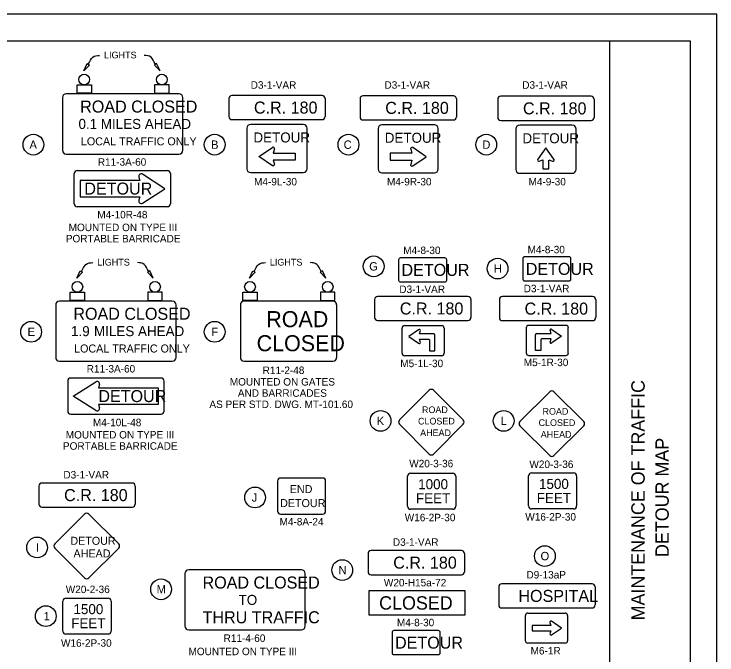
# Model space of a CAD drawing. Extents: x 1 to 1971, y -2 to 1107.
# Drawn here: x 1672.33 to 1685.46, y 1094.62 to 1106.6 of the extents above; entities that cross this region are included whole.
import ezdxf

# ---------------------------------------------------------------- set-up
doc = ezdxf.new("R2010")
doc.units = 0
for name, color, linetype in [('SH_Border', 7, 'Continuous'), ('SH_Cut_Line', 7, 'Continuous'), ('SH_Data', 7, 'Continuous'), ('SH_Text', 7, 'Continuous'), ('SN_P_Signs', 7, 'Continuous'), ('SN_P_Text', 7, 'Continuous')]:
    doc.layers.add(name, color=color, linetype=linetype)

msp = doc.modelspace()

# ---------------------------------------------------------------- linework, layer by layer
at = {"layer": 'SH_Border'}
msp.add_line((1683.463, 1085.101), (1683.463, 1106.101), dxfattribs=at)
msp.add_lwpolyline([(1652.963, 1106.101), (1684.963, 1106.101), (1684.963, 1085.101), (1652.963, 1085.101)], close=True, dxfattribs=at)
at = {"layer": 'SH_Cut_Line'}
msp.add_lwpolyline([(1651.463, 1084.601), (1685.463, 1084.601), (1685.463, 1106.601), (1651.463, 1106.601)], close=True, dxfattribs=at)
at = {"layer": 'SH_Text'}
for centre in [(1672.689, 1104.158), (1676.077, 1104.158), (1678.577, 1104.158), (1681.152, 1104.158), (1679.048, 1101.882), (1681.364, 1101.84), (1672.647, 1100.658), (1676.077, 1100.658), (1679.177, 1098.992), (1681.477, 1098.992), (1676.832, 1097.56), (1672.758, 1096.626), (1682.247, 1096.464), (1678.461, 1096.202), (1675.075, 1095.843), (1672.921, 1095.341)]:
    msp.add_circle(centre, 0.194, dxfattribs=at)
at = {"layer": 'SN_P_Signs'}
for p, q in [((1676.903, 1103.936), (1677.156, 1104.108)), ((1677.195, 1104.079), (1677.17, 1104.002)), ((1679.74, 1104.073), (1679.764, 1103.997)), ((1680.031, 1103.931), (1679.779, 1104.102)), ((1682.267, 1104.099), (1682.116, 1103.884)), ((1682.418, 1103.884), (1682.267, 1104.099)), ((1677.156, 1103.765), (1676.903, 1103.936)), ((1677.17, 1104.002), (1677.578, 1104.002)), ((1677.578, 1104.002), (1677.578, 1103.871)), ((1679.764, 1103.997), (1679.356, 1103.997)), ((1679.356, 1103.997), (1679.356, 1103.865)), ((1679.779, 1103.76), (1680.031, 1103.931)), ((1677.578, 1103.871), (1677.17, 1103.871)), ((1677.17, 1103.871), (1677.195, 1103.794)), ((1679.356, 1103.865), (1679.764, 1103.865)), ((1679.764, 1103.865), (1679.74, 1103.789)), ((1682.141, 1103.85), (1682.21, 1103.872)), ((1682.21, 1103.872), (1682.21, 1103.871)), ((1682.21, 1103.871), (1682.21, 1103.705)), ((1682.324, 1103.872), (1682.393, 1103.85)), ((1682.21, 1103.705), (1682.324, 1103.705)), ((1674.66, 1103.552), (1674.68, 1103.49)), ((1675.148, 1103.335), (1674.727, 1103.604)), ((1674.68, 1103.49), (1673.564, 1103.49)), ((1673.564, 1103.49), (1673.564, 1103.181)), ((1674.727, 1103.067), (1675.148, 1103.335)), ((1673.564, 1103.181), (1674.68, 1103.181)), ((1674.68, 1103.181), (1674.66, 1103.118)), ((1679.624, 1100.774), (1680.321, 1100.774)), ((1682.641, 1100.779), (1681.944, 1100.779)), ((1679.579, 1100.256), (1679.579, 1100.729)), ((1679.889, 1100.695), (1679.705, 1100.57)), ((1679.902, 1100.619), (1679.921, 1100.682)), ((1680.366, 1100.729), (1680.366, 1100.256)), ((1681.899, 1100.734), (1681.899, 1100.262)), ((1682.096, 1100.625), (1682.363, 1100.625)), ((1682.096, 1100.625), (1682.096, 1100.625)), ((1682.363, 1100.625), (1682.344, 1100.688)), ((1682.376, 1100.701), (1682.56, 1100.575)), ((1682.686, 1100.262), (1682.686, 1100.734)), ((1679.705, 1100.57), (1679.889, 1100.444)), ((1680.17, 1100.619), (1679.902, 1100.619)), ((1679.921, 1100.457), (1679.902, 1100.52)), ((1679.902, 1100.52), (1680.078, 1100.52)), ((1680.092, 1100.506), (1680.092, 1100.302)), ((1680.17, 1100.619), (1680.17, 1100.619)), ((1680.191, 1100.302), (1680.191, 1100.598)), ((1682.075, 1100.308), (1682.075, 1100.604)), ((1682.173, 1100.512), (1682.173, 1100.308)), ((1682.363, 1100.526), (1682.187, 1100.526)), ((1682.344, 1100.463), (1682.363, 1100.526)), ((1682.56, 1100.575), (1682.376, 1100.45)), ((1680.092, 1100.302), (1680.191, 1100.302)), ((1680.092, 1100.302), (1680.191, 1100.302)), ((1682.173, 1100.308), (1682.075, 1100.308)), ((1680.321, 1100.211), (1679.624, 1100.211)), ((1681.944, 1100.217), (1682.641, 1100.217)), ((1673.434, 1099.456), (1673.856, 1099.725)), ((1673.923, 1099.673), (1673.903, 1099.611)), ((1673.903, 1099.611), (1675.018, 1099.611)), ((1675.018, 1099.611), (1675.018, 1099.301)), ((1673.856, 1099.187), (1673.434, 1099.456)), ((1675.018, 1099.301), (1673.903, 1099.301)), ((1673.903, 1099.301), (1673.923, 1099.239)), ((1681.928, 1095.399), (1682.626, 1095.399)), ((1681.883, 1094.881), (1681.883, 1095.354)), ((1682.558, 1095.117), (1682.372, 1095.245)), ((1682.671, 1095.354), (1682.671, 1094.881)), ((1682.361, 1095.167), (1682.01, 1095.167)), ((1682.01, 1095.167), (1682.01, 1095.068)), ((1682.343, 1095.224), (1682.361, 1095.167)), ((1682.374, 1094.992), (1682.558, 1095.117)), ((1682.01, 1095.068), (1682.361, 1095.068)), ((1682.361, 1095.068), (1682.343, 1095.011)), ((1682.626, 1094.836), (1681.928, 1094.836))]:
    msp.add_line(p, q, dxfattribs=at)
for points in [[(1673.735, 1105.647), (1673.63, 1105.536), (1673.694, 1105.675)], [(1674.95, 1105.647), (1675.056, 1105.536), (1674.992, 1105.675)], [(1673.504, 1105.12), (1673.504, 1105.275), (1673.773, 1105.275), (1673.773, 1105.12)], [(1675.224, 1105.12), (1675.224, 1105.275), (1674.955, 1105.275), (1674.955, 1105.12)], [(1673.608, 1101.772), (1673.503, 1101.661), (1673.566, 1101.801)], [(1674.823, 1101.772), (1674.928, 1101.661), (1674.864, 1101.801)], [(1676.834, 1101.772), (1676.729, 1101.661), (1676.793, 1101.801)], [(1678.049, 1101.772), (1678.154, 1101.661), (1678.091, 1101.801)], [(1673.376, 1101.245), (1673.376, 1101.401), (1673.645, 1101.401), (1673.645, 1101.245)], [(1675.097, 1101.245), (1675.097, 1101.401), (1674.828, 1101.401), (1674.828, 1101.245)], [(1676.603, 1101.245), (1676.603, 1101.401), (1676.872, 1101.401), (1676.872, 1101.245)], [(1678.323, 1101.245), (1678.323, 1101.401), (1678.054, 1101.401), (1678.054, 1101.245)], [(1678.959, 1095.363), (1680.759, 1095.363), (1680.759, 1095.813), (1678.959, 1095.813)]]:
    msp.add_lwpolyline(points, close=True, dxfattribs=at)
for points in [[(1675.413, 1105.108), (1673.303, 1105.108)], [(1673.233, 1105.038), (1673.233, 1104.053)], [(1675.483, 1104.053), (1675.483, 1105.038)], [(1676.34, 1105.02), (1676.34, 1104.683)], [(1678.084, 1105.076), (1676.397, 1105.076)], [(1678.14, 1105.02), (1678.14, 1104.683)], [(1678.794, 1105.015), (1678.794, 1104.677)], [(1680.538, 1105.071), (1678.85, 1105.071)], [(1680.594, 1105.015), (1680.594, 1104.677)], [(1681.367, 1105.006), (1681.367, 1104.668)], [(1683.111, 1105.062), (1681.423, 1105.062)], [(1683.167, 1105.006), (1683.167, 1104.668)], [(1676.397, 1104.626), (1678.084, 1104.626)], [(1678.85, 1104.621), (1680.538, 1104.621)], [(1681.423, 1104.612), (1683.111, 1104.612)], [(1676.678, 1104.464), (1676.678, 1103.708)], [(1677.731, 1104.536), (1676.75, 1104.536)], [(1677.803, 1103.708), (1677.803, 1104.464)], [(1679.131, 1104.459), (1679.131, 1103.703)], [(1680.184, 1104.531), (1679.203, 1104.531)], [(1680.256, 1103.703), (1680.256, 1104.459)], [(1681.705, 1104.45), (1681.705, 1103.694)], [(1682.758, 1104.522), (1681.777, 1104.522)], [(1682.83, 1103.694), (1682.83, 1104.45)], [(1673.303, 1103.983), (1675.413, 1103.983)], [(1682.324, 1103.705), (1682.324, 1103.871)], [(1673.508, 1103.673), (1675.195, 1103.673)], [(1673.452, 1103.054), (1673.452, 1103.617)], [(1675.252, 1103.617), (1675.252, 1103.054)], [(1676.75, 1103.636), (1677.731, 1103.636)], [(1679.203, 1103.631), (1680.184, 1103.631)], [(1681.777, 1103.622), (1682.758, 1103.622)], [(1675.195, 1102.998), (1673.508, 1102.998)], [(1679.514, 1102.005), (1679.514, 1101.627)], [(1680.378, 1102.041), (1679.55, 1102.041)], [(1680.414, 1101.627), (1680.414, 1102.005)], [(1681.835, 1102.025), (1681.835, 1101.647)], [(1682.699, 1102.061), (1681.871, 1102.061)], [(1682.735, 1101.647), (1682.735, 1102.025)], [(1679.55, 1101.591), (1680.378, 1101.591)], [(1681.871, 1101.611), (1682.699, 1101.611)], [(1680.81, 1101.32), (1679.122, 1101.32)], [(1683.14, 1101.317), (1681.453, 1101.317)], [(1673.106, 1101.163), (1673.106, 1100.179)], [(1675.285, 1101.233), (1673.176, 1101.233)], [(1675.356, 1100.179), (1675.356, 1101.163)], [(1676.557, 1101.163), (1676.557, 1100.179)], [(1678.286, 1101.233), (1676.627, 1101.233)], [(1678.357, 1100.179), (1678.357, 1101.163)], [(1679.066, 1101.263), (1679.066, 1100.926)], [(1680.866, 1101.263), (1680.866, 1100.926)], [(1681.397, 1101.261), (1681.397, 1100.923)], [(1683.197, 1101.261), (1683.197, 1100.923)], [(1679.122, 1100.87), (1680.81, 1100.87)], [(1681.453, 1100.867), (1683.14, 1100.867)], [(1673.176, 1100.108), (1675.285, 1100.108)], [(1676.627, 1100.108), (1678.286, 1100.108)], [(1673.331, 1099.737), (1673.331, 1099.175)], [(1675.074, 1099.794), (1673.387, 1099.794)], [(1675.131, 1099.175), (1675.131, 1099.737)], [(1679.528, 1099.009), (1680.085, 1099.566)], [(1680.164, 1099.566), (1680.721, 1099.009)], [(1681.781, 1098.98), (1682.338, 1099.537)], [(1682.418, 1099.537), (1682.974, 1098.98)], [(1673.387, 1099.119), (1675.074, 1099.119)], [(1680.085, 1098.373), (1679.528, 1098.929)], [(1680.721, 1098.929), (1680.164, 1098.373)], [(1682.338, 1098.343), (1681.781, 1098.9)], [(1682.974, 1098.9), (1682.418, 1098.343)], [(1679.739, 1098.014), (1680.526, 1098.014)], [(1681.997, 1098.02), (1682.785, 1098.02)], [(1677.25, 1097.865), (1677.25, 1097.307)], [(1678.092, 1097.924), (1677.309, 1097.924)], [(1678.15, 1097.307), (1678.15, 1097.865)], [(1679.683, 1097.395), (1679.683, 1097.958)], [(1680.583, 1097.958), (1680.583, 1097.395)], [(1681.941, 1097.401), (1681.941, 1097.964)], [(1682.841, 1097.964), (1682.841, 1097.401)], [(1672.792, 1097.773), (1672.792, 1097.436)], [(1674.536, 1097.83), (1672.848, 1097.83)], [(1674.592, 1097.773), (1674.592, 1097.436)], [(1672.848, 1097.38), (1674.536, 1097.38)], [(1682.785, 1097.345), (1681.997, 1097.345)], [(1673.091, 1096.693), (1673.647, 1097.25)], [(1673.727, 1097.25), (1674.284, 1096.693)], [(1677.309, 1097.249), (1678.092, 1097.249)], [(1680.526, 1097.339), (1679.739, 1097.339)], [(1673.647, 1096.057), (1673.091, 1096.614)], [(1674.284, 1096.614), (1673.727, 1096.057)], [(1680.687, 1096.566), (1678.999, 1096.566)], [(1678.943, 1096.51), (1678.943, 1096.172)], [(1680.743, 1096.51), (1680.743, 1096.172)], [(1677.7, 1096.207), (1675.591, 1096.207)], [(1675.52, 1096.137), (1675.52, 1095.153)], [(1677.77, 1095.153), (1677.77, 1096.137)], [(1678.999, 1096.116), (1680.687, 1096.116)], [(1683.129, 1095.945), (1681.442, 1095.945)], [(1681.386, 1095.888), (1681.386, 1095.551)], [(1683.186, 1095.888), (1683.186, 1095.551)], [(1673.297, 1095.678), (1674.084, 1095.678)], [(1673.241, 1095.059), (1673.241, 1095.622)], [(1674.141, 1095.622), (1674.141, 1095.059)], [(1681.442, 1095.495), (1683.129, 1095.495)], [(1674.084, 1095.003), (1673.297, 1095.003)], [(1675.591, 1095.082), (1677.7, 1095.082)], [(1679.392, 1095.035), (1679.392, 1094.657)], [(1680.256, 1095.071), (1679.428, 1095.071)], [(1680.292, 1094.657), (1680.292, 1095.035)], [(1679.428, 1094.621), (1680.256, 1094.621)]]:
    msp.add_lwpolyline(points, dxfattribs=at)
for centre in [(1673.638, 1105.375), (1675.09, 1105.375), (1673.511, 1101.5), (1674.963, 1101.5), (1676.737, 1101.5), (1678.189, 1101.5)]:
    msp.add_circle(centre, 0.0998, dxfattribs=at)
for centre, radius, start, end in [((1673.303, 1105.038), 0.0703, 90, 180), ((1675.413, 1105.038), 0.0703, 0, 90), ((1676.397, 1105.02), 0.0563, 90, 180), ((1678.084, 1105.02), 0.0563, 0, 90), ((1678.85, 1105.015), 0.0563, 90, 180), ((1680.538, 1105.015), 0.0563, 0, 90), ((1681.423, 1105.006), 0.0563, 90, 180), ((1683.111, 1105.006), 0.0563, 0, 90), ((1676.397, 1104.683), 0.0563, 180, 270), ((1678.084, 1104.683), 0.0563, 270, 0), ((1678.85, 1104.677), 0.0563, 180, 270), ((1680.538, 1104.677), 0.0563, 270, 0), ((1681.423, 1104.668), 0.0563, 180, 270), ((1683.111, 1104.668), 0.0563, 270, 0), ((1676.75, 1104.464), 0.072, 90, 180), ((1677.731, 1104.464), 0.072, 0, 90), ((1679.203, 1104.459), 0.072, 90, 180), ((1680.184, 1104.459), 0.072, 0, 90), ((1681.777, 1104.45), 0.072, 90, 180), ((1682.758, 1104.45), 0.072, 0, 90), ((1673.303, 1104.053), 0.0703, 180, 270), ((1675.413, 1104.053), 0.0703, 270, 0), ((1677.17, 1104.087), 0.0257, 342.1992, 124.1969), ((1679.764, 1104.081), 0.0257, 55.8031, 197.8008), ((1677.17, 1103.787), 0.0257, 235.8031, 17.8008), ((1679.764, 1103.781), 0.0257, 162.1992, 304.1969), ((1682.134, 1103.871), 0.0222, 144.9207, 287.6378), ((1682.4, 1103.871), 0.0222, 252.3622, 35.0792), ((1673.508, 1103.617), 0.0563, 90, 180), ((1675.195, 1103.617), 0.0563, 0, 90), ((1676.75, 1103.708), 0.072, 180, 270), ((1677.731, 1103.708), 0.072, 270, 0), ((1679.203, 1103.703), 0.072, 180, 270), ((1680.184, 1103.703), 0.072, 270, 0), ((1681.777, 1103.694), 0.072, 180, 270), ((1682.758, 1103.694), 0.072, 270, 0), ((1674.702, 1103.566), 0.045, 57.4891, 197.8189), ((1673.508, 1103.054), 0.0563, 180, 270), ((1674.702, 1103.104), 0.045, 162.1811, 302.5109), ((1675.195, 1103.054), 0.0563, 270, 360), ((1679.55, 1102.005), 0.036, 90, 180), ((1680.378, 1102.005), 0.036, 0, 90), ((1681.871, 1102.025), 0.036, 90, 180), ((1682.699, 1102.025), 0.036, 0, 90), ((1679.55, 1101.627), 0.036, 180, 270), ((1680.378, 1101.627), 0.036, 270, 0), ((1681.871, 1101.647), 0.036, 180, 270), ((1682.699, 1101.647), 0.036, 270, 0), ((1679.122, 1101.263), 0.0563, 90, 180), ((1680.81, 1101.263), 0.0563, 0, 90), ((1681.453, 1101.261), 0.0563, 90, 180), ((1683.14, 1101.261), 0.0563, 0, 90), ((1673.176, 1101.163), 0.0703, 90, 180), ((1675.285, 1101.163), 0.0703, 0, 90), ((1676.627, 1101.163), 0.0705, 90, 180), ((1678.286, 1101.163), 0.0705, 0, 90), ((1679.122, 1100.926), 0.0563, 180, 270), ((1680.81, 1100.926), 0.0563, 270, 0), ((1681.453, 1100.923), 0.0563, 180, 270), ((1683.14, 1100.923), 0.0563, 270, 0), ((1679.624, 1100.729), 0.045, 90, 180), ((1680.321, 1100.729), 0.045, 0, 90), ((1681.944, 1100.734), 0.045, 90, 180), ((1682.642, 1100.734), 0.045, 0, 90), ((1679.902, 1100.682), 0.0188, 0.0017, 134.9999), ((1682.096, 1100.604), 0.0211, 90, 180), ((1682.363, 1100.688), 0.0188, 45.0001, 179.9983), ((1680.078, 1100.506), 0.014, 0, 90), ((1680.17, 1100.598), 0.0211, 0, 90), ((1682.187, 1100.512), 0.014, 90, 180), ((1679.902, 1100.457), 0.0188, 225.0001, 0.0017), ((1682.363, 1100.463), 0.0188, 179.9983, 314.9999), ((1679.624, 1100.256), 0.045, 180, 270), ((1680.321, 1100.256), 0.045, 270, 360), ((1681.944, 1100.262), 0.045, 180, 270), ((1682.642, 1100.262), 0.045, 270, 0), ((1673.176, 1100.179), 0.0703, 180, 270), ((1675.285, 1100.179), 0.0703, 270, 0), ((1676.627, 1100.179), 0.0705, 180, 270), ((1678.286, 1100.179), 0.0705, 270, 0), ((1673.387, 1099.737), 0.0563, 90, 180), ((1673.88, 1099.687), 0.045, 342.1811, 122.5109), ((1675.074, 1099.737), 0.0563, 0, 90), ((1680.125, 1099.526), 0.0562, 45, 135), ((1682.378, 1099.497), 0.0562, 45, 135), ((1673.88, 1099.225), 0.045, 237.4891, 17.8189), ((1673.387, 1099.175), 0.0563, 180, 270), ((1675.074, 1099.175), 0.0563, 270, 0), ((1679.568, 1098.969), 0.0562, 135, 225), ((1680.682, 1098.969), 0.0562, 315, 45), ((1681.821, 1098.94), 0.0562, 135, 225), ((1682.935, 1098.94), 0.0562, 315, 45), ((1680.125, 1098.412), 0.0562, 225, 315), ((1682.378, 1098.383), 0.0562, 225, 315), ((1679.739, 1097.958), 0.0563, 90, 180), ((1680.526, 1097.958), 0.0563, 0, 90), ((1681.997, 1097.964), 0.0563, 90, 180), ((1682.785, 1097.964), 0.0563, 0, 90), ((1677.309, 1097.865), 0.0585, 90, 180), ((1678.092, 1097.865), 0.0585, 0, 90), ((1672.848, 1097.773), 0.0563, 90, 180), ((1674.536, 1097.773), 0.0563, 0, 90), ((1672.848, 1097.436), 0.0563, 180, 270), ((1674.536, 1097.436), 0.0563, 270, 0), ((1679.739, 1097.395), 0.0563, 180, 270), ((1680.526, 1097.395), 0.0563, 270, 0), ((1681.997, 1097.401), 0.0563, 180, 270), ((1682.785, 1097.401), 0.0563, 270, 0), ((1673.687, 1097.21), 0.0562, 45, 135), ((1677.309, 1097.307), 0.0585, 180, 270), ((1678.092, 1097.307), 0.0585, 270, 0), ((1673.13, 1096.653), 0.0562, 135, 225), ((1674.244, 1096.653), 0.0562, 315, 45), ((1678.999, 1096.51), 0.0563, 90, 180), ((1680.687, 1096.51), 0.0563, 0, 90), ((1675.591, 1096.137), 0.0703, 90, 180), ((1677.7, 1096.137), 0.0703, 0, 90), ((1678.999, 1096.172), 0.0563, 180, 270), ((1680.687, 1096.172), 0.0563, 270, 0), ((1673.687, 1096.097), 0.0562, 225, 315), ((1681.442, 1095.888), 0.0563, 90, 180), ((1683.129, 1095.888), 0.0563, 0, 90), ((1673.297, 1095.622), 0.0563, 90, 180), ((1674.084, 1095.622), 0.0563, 0, 90), ((1681.442, 1095.551), 0.0563, 180, 270), ((1683.129, 1095.551), 0.0563, 270, 0), ((1681.928, 1095.354), 0.045, 90, 180), ((1682.626, 1095.354), 0.045, 0, 90), ((1682.361, 1095.23), 0.0188, 55.4112, 197.2046), ((1675.591, 1095.153), 0.0703, 180, 270), ((1677.7, 1095.153), 0.0703, 270, 0), ((1673.297, 1095.059), 0.0563, 180, 270), ((1674.084, 1095.059), 0.0563, 270, 0), ((1679.428, 1095.035), 0.036, 90, 180), ((1680.256, 1095.035), 0.036, 0, 90), ((1682.361, 1095.005), 0.0188, 162.7954, 315.0096), ((1681.928, 1094.881), 0.045, 180, 270), ((1682.626, 1094.881), 0.045, 270, 360), ((1679.428, 1094.657), 0.036, 180, 270), ((1680.256, 1094.657), 0.036, 270, 0)]:
    msp.add_arc(centre, radius, start, end, dxfattribs=at)
for points in [[(1673.715, 1105.661), (1673.747, 1105.709), (1673.78, 1105.823), (1673.884, 1105.825), (1673.925, 1105.827)], [(1674.971, 1105.661), (1674.938, 1105.709), (1674.905, 1105.823), (1674.801, 1105.825), (1674.76, 1105.827)], [(1673.587, 1101.786), (1673.62, 1101.834), (1673.653, 1101.948), (1673.757, 1101.95), (1673.798, 1101.952)], [(1674.844, 1101.786), (1674.811, 1101.834), (1674.778, 1101.948), (1674.674, 1101.95), (1674.633, 1101.952)], [(1676.813, 1101.786), (1676.846, 1101.834), (1676.879, 1101.948), (1676.983, 1101.95), (1677.024, 1101.952)], [(1678.07, 1101.786), (1678.037, 1101.834), (1678.004, 1101.948), (1677.9, 1101.95), (1677.859, 1101.952)]]:
    msp.add_open_spline(points, degree=3, dxfattribs=at)

# ---------------------------------------------------------------- texts
at = {"layer": 'SH_Data'}
for s, p in [('MAINTENANCE OF TRAFFIC', (1684.113, 1095.262)), ('DETOUR MAP', (1684.563, 1096.447))]:
    msp.add_text(s, height=0.25, rotation=90, dxfattribs=at).set_placement(p)
at = {"layer": 'SH_Text'}
for s, p in [('A', (1672.616, 1104.08)), ('B', (1676.01, 1104.08)), ('C', (1678.487, 1104.08)), ('D', (1681.079, 1104.08)), ('G', (1678.964, 1101.804)), ('H', (1681.294, 1101.762)), ('E', (1672.58, 1100.58)), ('F', (1676.016, 1100.58)), ('K', (1679.105, 1098.914)), ('L', (1681.42, 1098.914)), ('J', (1676.769, 1097.482)), ('I', (1672.738, 1096.548)), ('O', (1682.167, 1096.386)), ('N', (1678.391, 1096.124)), ('M', (1674.992, 1095.765)), ('1', (1672.881, 1095.263))]:
    msp.add_text(s, height=0.156, dxfattribs=at).set_placement(p)
at = {"layer": 'SN_P_Signs'}
for s, height, p in [('LIGHTS', 0.126, (1674.009, 1105.771)), ('ROAD CLOSED', 0.225, (1673.563, 1104.758)), ('C.R. 180', 0.225, (1676.811, 1104.739)), ('C.R. 180', 0.225, (1679.265, 1104.733)), ('C.R. 180', 0.225, (1681.838, 1104.724)), ('0.1', 0.1875, (1673.532, 1104.452)), ('MILES AHEAD', 0.1875, (1673.949, 1104.452)), ('DETOUR', 0.1875, (1676.801, 1104.199)), ('DETOUR', 0.1875, (1679.255, 1104.193)), ('DETOUR', 0.1875, (1681.828, 1104.184)), ('LOCAL TRAFFIC ONLY', 0.15, (1673.577, 1104.145)), ('DETOUR', 0.225, (1673.641, 1103.224)), ('LIGHTS', 0.126, (1673.882, 1101.897)), ('LIGHTS', 0.126, (1677.108, 1101.897)), ('DETOUR', 0.225, (1681.89, 1101.723)), ('DETOUR', 0.225, (1679.568, 1101.704)), ('C.R. 180', 0.225, (1679.537, 1100.982)), ('C.R. 180', 0.225, (1681.868, 1100.979)), ('ROAD CLOSED', 0.225, (1673.436, 1100.883)), ('ROAD', 0.3, (1677.041, 1100.745)), ('1.9', 0.1875, (1673.393, 1100.577)), ('MILES AHEAD', 0.1875, (1673.822, 1100.577)), ('CLOSED', 0.3, (1676.861, 1100.295)), ('LOCAL TRAFFIC ONLY', 0.15, (1673.45, 1100.271)), ('DETOUR', 0.225, (1673.903, 1099.344)), ('ROAD', 0.125, (1679.951, 1099.138)), ('ROAD', 0.125, (1682.204, 1099.108)), ('CLOSED', 0.125, (1679.877, 1098.925)), ('CLOSED', 0.125, (1682.13, 1098.896)), ('AHEAD', 0.125, (1679.917, 1098.707)), ('AHEAD', 0.125, (1682.17, 1098.677)), ('1000', 0.1875, (1679.88, 1097.714)), ('1500', 0.1875, (1682.138, 1097.72)), ('END', 0.15, (1677.48, 1097.642)), ('C.R. 180', 0.225, (1673.263, 1097.492)), ('FEET', 0.1875, (1679.838, 1097.452)), ('FEET', 0.1875, (1682.096, 1097.457)), ('DETOUR', 0.15, (1677.299, 1097.38)), ('DETOUR', 0.15, (1673.38, 1096.675)), ('AHEAD', 0.15, (1673.438, 1096.438)), ('C.R. 180', 0.225, (1679.414, 1096.229)), ('ROAD CLOSED', 0.225, (1675.85, 1095.857)), ('HOSPITAL', 0.225, (1681.753, 1095.607)), ('TO', 0.1875, (1676.524, 1095.551)), ('CLOSED', 0.25, (1679.15, 1095.463)), ('1500', 0.1875, (1673.438, 1095.378)), ('THRU TRAFFIC', 0.225, (1675.851, 1095.207)), ('FEET', 0.1875, (1673.396, 1095.115)), ('DETOUR', 0.225, (1679.447, 1094.733))]:
    msp.add_text(s, height=height, dxfattribs=at).set_placement(p)
at = {"layer": 'SN_P_Text'}
for s, p in [('D3-1-VAR', (1676.75, 1105.204)), ('D3-1-VAR', (1679.25, 1105.204)), ('D3-1-VAR', (1681.825, 1105.204)), ('R11-3A-60', (1673.893, 1103.764)), ('M4-9L-30', (1676.813, 1103.396)), ('M4-9R-30', (1679.297, 1103.396)), ('M4-9-30', (1681.942, 1103.396)), ('M4-10R-48', (1673.884, 1102.779)), ('MOUNTED ON TYPE III', (1673.348, 1102.541)), ('PORTABLE BARRICADE', (1673.295, 1102.331)), ('M4-8-30', (1679.6, 1102.112)), ('M4-8-30', (1681.924, 1102.126)), ('D3-1-VAR', (1679.528, 1101.384)), ('D3-1-VAR', (1681.852, 1101.398)), ('M5-1L-30', (1679.546, 1099.997)), ('M5-1R-30', (1681.854, 1100.016)), ('R11-3A-60', (1673.686, 1099.897)), ('R11-2-48', (1676.973, 1099.869)), ('MOUNTED ON GATES', (1676.36, 1099.653)), ('AND BARRICADES ', (1676.51, 1099.443)), ('AS PER STD. DWG. MT-101.60', (1675.978, 1099.233)), ('M4-10L-48', (1673.801, 1098.893)), ('MOUNTED ON TYPE III', (1673.294, 1098.663)), ('PORTABLE BARRICADE', (1673.241, 1098.453)), ('W20-3-36', (1679.713, 1098.125)), ('W20-3-36', (1681.959, 1098.111)), ('D3-1-VAR', (1673.25, 1097.915)), ('W16-2P-30', (1679.629, 1097.116)), ('W16-2P-30', (1681.882, 1097.128)), ('M4-8A-24', (1677.289, 1097.037)), ('D3-1-VAR', (1679.407, 1096.656)), ('D9-13aP', (1681.903, 1096.045)), ('W20-H15a-72', (1679.239, 1095.897)), ('W20-2-36', (1673.294, 1095.772)), ('M4-8-30', (1679.483, 1095.152)), ('R11-4-60', (1676.244, 1094.859)), ('W16-2P-30', (1673.205, 1094.769)), ('MOUNTED ON TYPE III', (1675.588, 1094.611)), ('M6-1R', (1681.981, 1094.624))]:
    msp.add_text(s, height=0.14, dxfattribs=at).set_placement(p)

doc.saveas('drawing.dxf')
